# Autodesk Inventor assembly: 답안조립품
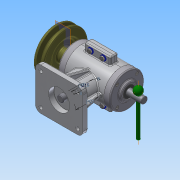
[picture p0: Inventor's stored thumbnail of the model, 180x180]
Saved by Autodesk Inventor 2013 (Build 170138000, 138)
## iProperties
Created: 2015-12
Part Number: 답안조립품
Document SubType Name: Assembly
Designer: Administrator
Author: Administrator
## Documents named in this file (19)
- C:\Users\Administrator\Desktop\351208V1038\답안조립품.iam
- C:\Users\Administrator\Desktop\351208V1038\V-벨트풀리.ipt
- C:\Users\Administrator\Desktop\351208V1038\너트 M4.ipt
- C:\Users\Administrator\Desktop\351208V1038\뒤커버.ipt
- C:\Users\Administrator\Desktop\351208V1038\레바.ipt
- C:\Users\Administrator\Desktop\351208V1038\멈춤나사 M3x8.ipt
- C:\Users\Administrator\Desktop\351208V1038\베어링 6201.ipt
- C:\Users\Administrator\Desktop\351208V1038\베어링 6202.ipt
- C:\Users\Administrator\Desktop\351208V1038\본체.ipt
- C:\Users\Administrator\Desktop\351208V1038\본체커버.ipt
- C:\Users\Administrator\Desktop\351208V1038\볼트 M3x0.5x8.ipt
- C:\Users\Administrator\Desktop\351208V1038\볼트 M4 x 16.ipt
- C:\Users\Administrator\Desktop\351208V1038\스프링.ipt
- C:\Users\Administrator\Desktop\351208V1038\슬라이드.ipt
- C:\Users\Administrator\Desktop\351208V1038\앞커버.ipt
- C:\Users\Administrator\Desktop\351208V1038\오일실 12 22 7.ipt
- C:\Users\Administrator\Desktop\351208V1038\와셔 ST 4-100.ipt
- C:\Users\Administrator\Desktop\351208V1038\키 4 x 4 x 18.ipt
- C:\Users\Administrator\Desktop\351208V1038\편심축.ipt
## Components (13 placed, 4 different names)
1. V-벨트풀리:1 — 플러쉬:1, 각도:1
2. ISO 4032 M4:1
3. ISO 4762 M4 x 16:1
4. ISO 7091 ST 4 - 100 HV:1
5. ISO 4762 M4 x 16:2
6. ISO 4762 M4 x 16:3
7. ISO 4762 M4 x 16:4
8. ISO 7091 ST 4 - 100 HV:2
9. ISO 7091 ST 4 - 100 HV:3
10. ISO 7091 ST 4 - 100 HV:4
11. ISO 4032 M4:2
12. ISO 4032 M4:3
13. ISO 4032 M4:4
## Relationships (2: Flush 1, Angle 1)
- 플러쉬:1 [Flush]: V-벨트풀리:1
- 각도:1 [Angle]: V-벨트풀리:1
